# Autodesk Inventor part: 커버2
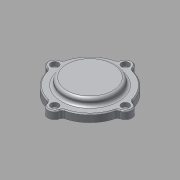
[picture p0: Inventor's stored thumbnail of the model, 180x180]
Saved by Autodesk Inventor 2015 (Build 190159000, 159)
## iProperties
Company: 한국ATC센터
Created: 2015-12
Part Number: 커버2
Document SubType Name: Modeling
Designer: mdu
Density: 2.71 g/cm^3
Material: 알루미늄 6061
Appearance: 알루미늄 - 평지
Author: mdu
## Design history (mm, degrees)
sketch "스케치1"
  geometry: C1 r 1.621 at (0, 6.75) reference; C2 r 1.621 at (-37, -30.25) reference; C3 r 1.621 at (0, -67.25) reference; C4 r 1.621 at (37, -30.25) reference; C5 r 10 at (0, -30.25) reference; C6 r 12 at (0, -30.25); C7 r 24.5 at (0, -30.25) reference; A1 r 3 centre (-38.77, -20.408) between (-38.239, -23.361) and (-35.862, -21.146) reference; A2 r 7 centre (-37, -30.25) between (-38.239, -23.361) and (-38.239, -37.139) reference; A3 r 3 centre (-38.77, -40.092) between (-35.862, -39.354) and (-38.239, -37.139) reference; A4 r 37 centre (0, -30.25) between (-35.862, -39.354) and (-9.104, -66.113) reference; A5 r 3 centre (-9.842, -69.02) between (-6.889, -68.489) and (-9.104, -66.113) reference; A6 r 7 centre (0, -67.25) between (-6.889, -68.489) and (6.889, -68.489) reference; A7 r 3 centre (9.842, -69.02) between (9.104, -66.112) and (6.889, -68.489) reference; A8 r 37 centre (0, -30.25) between (9.104, -66.112) and (35.863, -39.354) reference; A9 r 3 centre (38.77, -40.092) between (38.239, -37.139) and (35.863, -39.354) reference; A10 r 7 centre (37, -30.25) between (38.239, -37.139) and (38.239, -23.361) reference; A11 r 3 centre (38.77, -20.408) between (35.863, -21.146) and (38.239, -23.361) reference; A12 r 37 centre (0, -30.25) between (35.863, -21.146) and (9.104, 5.612) reference; A13 r 3 centre (9.842, 8.52) between (6.889, 7.989) and (9.104, 5.612) reference; A14 r 7 centre (0, 6.75) between (6.889, 7.989) and (-6.889, 7.989) reference; A15 r 3 centre (-9.842, 8.52) between (-9.104, 5.612) and (-6.889, 7.989) reference; A16 r 37 centre (0, -30.25) between (-9.104, 5.612) and (-35.862, -21.146) reference; 1 further point
  constraints: 1 centre point, 1 coincident
  dimensions: "d2" = 2 radial gap between concentric circles of C6 C5
extrude "돌출1" new body sketch "스케치1" distance "d0" = 8; taper "d1" = 0 deg
sketch "스케치2"
  geometry: C1 r 23.5 at (0, -30.25) reference; C2 r 12 at (0, -30.25) reference; 1 further point
extrude "돌출2" join sketch "스케치2" distance "d4" = 5; taper "d5" = 0 deg
sketch "스케치3"
  geometry: C1 r 23.5 at (0, 0) reference; C2 r 20.5 at (0, 0); 1 further point
  constraints: 1 centre point
  dimensions: "d6" = 3 radial gap between concentric circles of C2 C1
node "작업 평면1"
extrude "돌출3" join sketch "스케치3" stored distance "d7" = 5; taper "d8" = 0 deg
fillet "모깎기1" dims "d9" = 3
sketch "스케치4"
  geometry: C1 r 12 at (0, -30.25) reference; C2 r 27 at (0, -30.25); 1 further point
  constraints: 1 centre point
  dimensions: "d10" = 15 radial gap between concentric circles of C1 C2
extrude "돌출4" join sketch "스케치4" distance "d11" = 7; taper "d12" = 0 deg
fillet "모깎기2" dims "d13" = 3
chamfer "모따기1" distance "d14" = 1; stored, may be unused: second distance "d15" = 2, angle "d16" = 45 deg
node "작업점1"
  node "작업축1"
chamfer "모따기2" distance "d24" = 1; stored, may be unused: second distance "d25" = 2, angle "d26" = 45 deg
hole "구멍6" diameter "d43" = 4.5; stored, may be unused: countersink angle "d47" = 90 deg, drill point angle "d49" = 118 deg; dims "d41" = 10, "d42" = 10, "d44" = 6, "d45" = 8, "d46" = 4.4, "d48" = 8
fillet "모깎기4" dims "d60" = 3
node "솔리드1"
pattern_circular "원형 패턴1" dims angle "d51" = 360 deg
node "참조1"
node "참조2"
